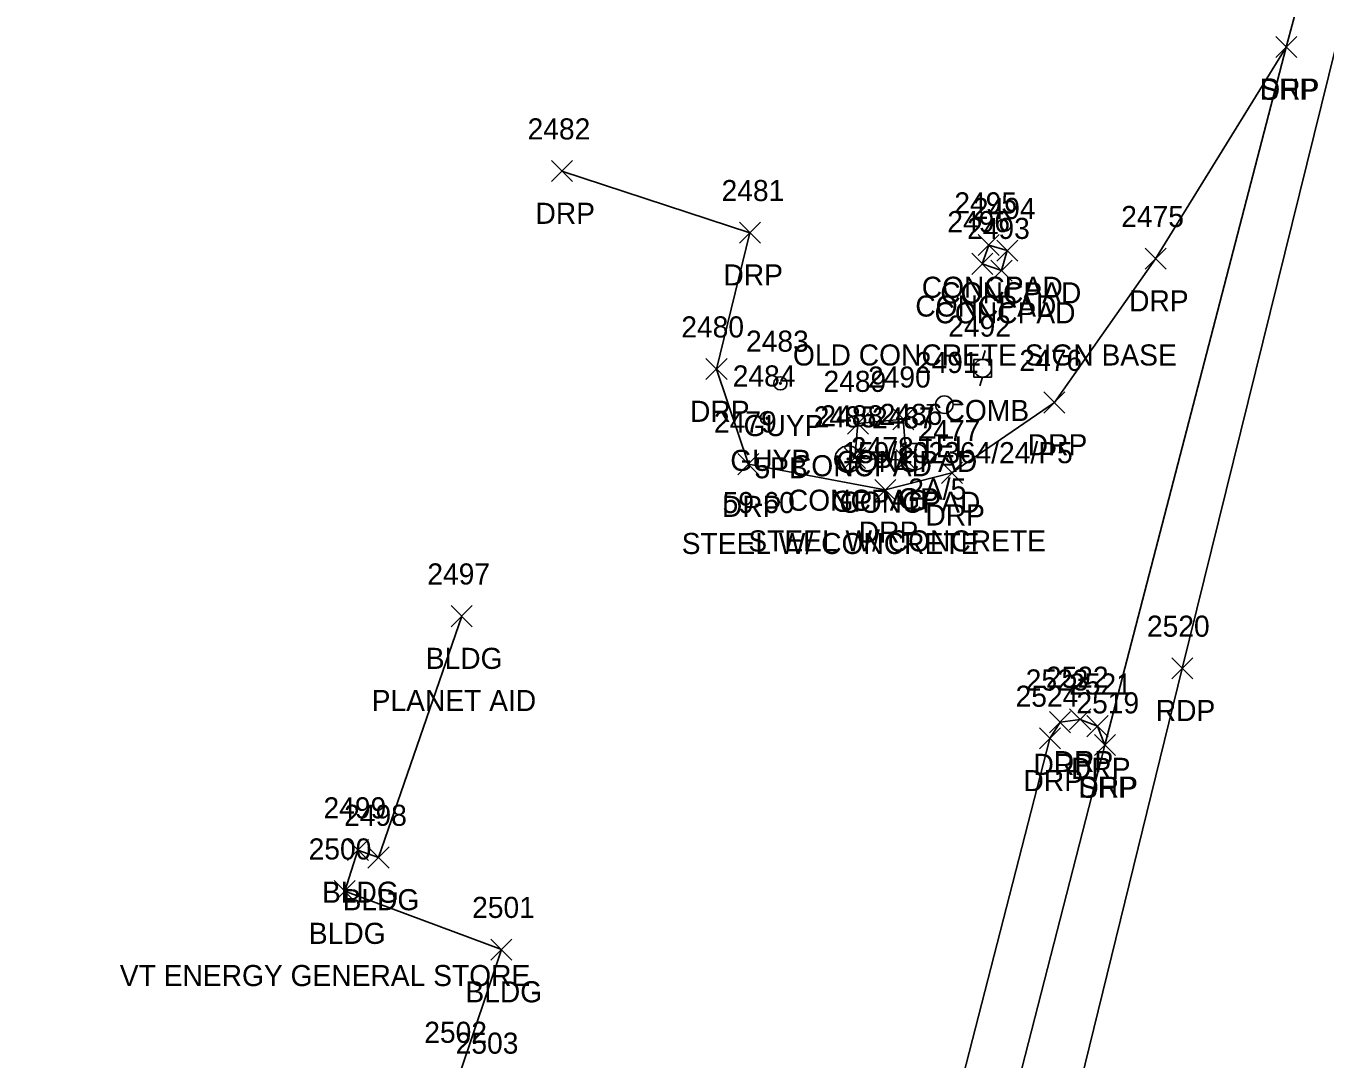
# Model space of a CAD drawing. Extents: x 1443071 to 1445292, y 614024 to 622563.
# Drawn here: x 1444043.4 to 1444166.6, y 620486.4 to 620584.3 of the extents above; entities that cross this region are included whole.
import ezdxf

# ---------------------------------------------------------------- set-up
doc = ezdxf.new("R2010")
doc.units = 0
for name, color, linetype in [('L_A', 7, 'Continuous'), ('L_C', 7, 'Continuous'), ('L_I', 7, 'Continuous'), ('L_TIC', 7, 'Continuous'), ('LBC', 7, 'Continuous'), ('LS', 7, 'Continuous'), ('P_A', 7, 'Continuous'), ('P_I', 7, 'Continuous'), ('P_TIC', 7, 'Continuous'), ('PET', 7, 'Continuous'), ('PSP', 7, 'Continuous'), ('R_A', 7, 'Continuous'), ('R_C', 7, 'Continuous'), ('R_I', 7, 'Continuous'), ('R_TIC', 7, 'Continuous'), ('RDP', 7, 'Continuous'), ('RGP', 7, 'Continuous'), ('U_A', 7, 'Continuous'), ('U_C', 7, 'Continuous'), ('U_I', 7, 'Continuous'), ('UP', 7, 'Continuous'), ('UPGW', 7, 'Continuous')]:
    doc.layers.add(name, color=color, linetype=linetype)

msp = doc.modelspace()

# ---------------------------------------------------------------- linework, layer by layer
at = {"layer": 'L_TIC'}
for points in [[(1444133.74, 620562.58), (1444135.74, 620564.58)], [(1444135.74, 620562.58), (1444133.74, 620564.58)], [(1444135.5, 620562.05), (1444137.5, 620564.05)], [(1444137.5, 620562.05), (1444135.5, 620564.05)], [(1444133.13, 620560.8), (1444135.13, 620562.8)], [(1444135.13, 620560.8), (1444133.13, 620562.8)], [(1444133.13, 620560.8), (1444135.13, 620562.8)], [(1444135.13, 620560.8), (1444133.13, 620562.8)], [(1444134.95, 620560.16), (1444136.95, 620562.16)], [(1444136.95, 620560.16), (1444134.95, 620562.16)], [(1444134.95, 620560.16), (1444136.95, 620562.16)], [(1444136.95, 620560.16), (1444134.95, 620562.16)], [(1444125.64, 620546.07), (1444127.64, 620548.07)], [(1444127.64, 620546.07), (1444125.64, 620548.07)], [(1444125.64, 620546.07), (1444127.64, 620548.07)], [(1444127.64, 620546.07), (1444125.64, 620548.07)], [(1444121.34, 620545.66), (1444123.34, 620547.66)], [(1444123.34, 620545.66), (1444121.34, 620547.66)], [(1444121.04, 620542.39), (1444123.04, 620544.39)], [(1444123.04, 620542.39), (1444121.04, 620544.39)], [(1444125.93, 620542.2), (1444127.93, 620544.2)], [(1444127.93, 620542.2), (1444125.93, 620544.2)], [(1444125.93, 620542.2), (1444127.93, 620544.2)], [(1444127.93, 620542.2), (1444125.93, 620544.2)], [(1444083.75, 620527.4), (1444085.75, 620529.4)], [(1444085.75, 620527.4), (1444083.75, 620529.4)], [(1444073.91, 620505.23), (1444075.91, 620507.23)], [(1444075.91, 620505.23), (1444073.91, 620507.23)], [(1444075.86, 620504.52), (1444077.86, 620506.52)], [(1444077.86, 620504.52), (1444075.86, 620506.52)], [(1444072.66, 620501.33), (1444074.66, 620503.33)], [(1444074.66, 620501.33), (1444072.66, 620503.33)], [(1444087.51, 620495.79), (1444089.51, 620497.79)], [(1444089.51, 620495.79), (1444087.51, 620497.79)]]:
    msp.add_lwpolyline(points, dxfattribs=at)
at = {"layer": 'LBC'}
msp.add_lwpolyline([(1444084.75, 620528.4), (1444076.86, 620505.52), (1444074.91, 620506.23), (1444073.66, 620502.33), (1444088.51, 620496.79), (1444084.54, 620484.95), (1444087.52, 620483.92), (1444085.41, 620477.91), (1444091.99, 620475.69), (1444085.33, 620455.76)], dxfattribs=at)
at = {"layer": 'LS'}
for points in [[(1444135.95, 620561.16), (1444136.5, 620563.05), (1444134.74, 620563.58), (1444134.13, 620561.8)], [(1444135.95, 620561.16), (1444134.13, 620561.8)], [(1444126.93, 620543.2), (1444122.04, 620543.39), (1444122.34, 620546.66), (1444126.64, 620547.07)], [(1444126.93, 620543.2), (1444126.64, 620547.07)]]:
    msp.add_lwpolyline(points, dxfattribs=at)
at = {"layer": 'P_TIC'}
for points in [[(1444161.97, 620581.35), (1444163.97, 620583.35)], [(1444163.97, 620581.35), (1444161.97, 620583.35)], [(1444152.1, 620522.45), (1444154.1, 620524.45)], [(1444154.1, 620522.45), (1444152.1, 620524.45)], [(1444144.76, 620515.18), (1444146.76, 620517.18)], [(1444146.76, 620515.18), (1444144.76, 620517.18)]]:
    msp.add_lwpolyline(points, dxfattribs=at)
at = {"layer": 'PET'}
msp.add_lwpolyline([(1444350.41, 621238.76), (1444319.14, 621126.97), (1444291.55, 621028.33), (1444258.02, 620908.98), (1444225.45, 620794.19), (1444210.22, 620737.59), (1444176.75, 620619.09), (1444153.1, 620523.45), (1444139.28, 620467.17), (1444131.97, 620435.45), (1444113.12, 620363.38), (1444103.37, 620315.76), (1444093.47, 620268.1), (1444084.86, 620222.29), (1444073.72, 620159.9), (1444065.08, 620092.83), (1444054.27, 620016.44), (1444048.57, 619960.86), (1444043.42, 619916.17), (1444073.05, 619913.75)], dxfattribs=at)
at = {"layer": 'PSP'}
msp.add_lwpolyline([(1444173.15, 620620.17), (1444162.97, 620582.35), (1444145.76, 620516.18), (1444133.67, 620469.15), (1444125.56, 620436.17), (1444114.52, 620389.82), (1444108.73, 620364.47), (1444098.18, 620317.14), (1444089.01, 620271.12), (1444079.56, 620223.77), (1444069.05, 620160.45), (1444059.79, 620093.6), (1444051.39, 620014.62), (1444046.92, 619961.11), (1444044.18, 619924.22), (1444043.48, 619922.84), (1444043.42, 619916.17)], dxfattribs=at)
at = {"layer": 'R_TIC'}
for points in [[(1444161.97, 620581.35), (1444163.97, 620583.35)], [(1444163.97, 620581.35), (1444161.97, 620583.35)], [(1444093.26, 620569.59), (1444095.26, 620571.59)], [(1444095.26, 620569.59), (1444093.26, 620571.59)], [(1444111.09, 620563.75), (1444113.09, 620565.75)], [(1444113.09, 620563.75), (1444111.09, 620565.75)], [(1444149.57, 620561.29), (1444151.57, 620563.29)], [(1444151.57, 620561.29), (1444149.57, 620563.29)], [(1444107.92, 620550.82), (1444109.92, 620552.82)], [(1444109.92, 620550.82), (1444107.92, 620552.82)], [(1444139.97, 620547.65), (1444141.97, 620549.65)], [(1444141.97, 620547.65), (1444139.97, 620549.65)], [(1444110.94, 620541.81), (1444112.94, 620543.81)], [(1444112.94, 620541.81), (1444110.94, 620543.81)], [(1444130.25, 620540.99), (1444132.25, 620542.99)], [(1444132.25, 620540.99), (1444130.25, 620542.99)], [(1444123.93, 620539.37), (1444125.93, 620541.37)], [(1444125.93, 620539.37), (1444123.93, 620541.37)], [(1444140.51, 620517.35), (1444142.51, 620519.35)], [(1444142.51, 620517.35), (1444140.51, 620519.35)], [(1444142.42, 620517.61), (1444144.42, 620519.61)], [(1444144.42, 620517.61), (1444142.42, 620519.61)], [(1444144.06, 620516.97), (1444146.06, 620518.97)], [(1444146.06, 620516.97), (1444144.06, 620518.97)], [(1444139.55, 620515.81), (1444141.55, 620517.81)], [(1444141.55, 620515.81), (1444139.55, 620517.81)], [(1444144.76, 620515.18), (1444146.76, 620517.18)], [(1444146.76, 620515.18), (1444144.76, 620517.18)]]:
    msp.add_lwpolyline(points, dxfattribs=at)
at = {"layer": 'RDP'}
for points in [[(1444162.97, 620582.35), (1444150.57, 620562.29), (1444140.97, 620548.65), (1444131.25, 620541.99), (1444124.93, 620540.37), (1444111.94, 620542.81), (1444108.92, 620551.82), (1444112.09, 620564.75), (1444094.26, 620570.59)], [(1444145.76, 620516.18), (1444145.06, 620517.97), (1444143.42, 620518.61), (1444141.51, 620518.35), (1444140.55, 620516.81), (1444128.49, 620469.93), (1444120.28, 620437.57), (1444109.05, 620390.35), (1444109.61, 620388.46), (1444110.93, 620387.66), (1444112.9, 620387.9), (1444114.52, 620389.82)]]:
    msp.add_lwpolyline(points, dxfattribs=at)
at = {"layer": 'RGP'}
for p, q in [((1444121.4, 620543.29), (1444121.4, 620543.29)), ((1444127.72, 620543.53), (1444127.72, 620543.53))]:
    msp.add_line(p, q, dxfattribs=at)
for centre, radius in [((1444121.4, 620543.29), 1.25), ((1444127.72, 620543.53), 1.25), ((1444121.4, 620543.29), 0.0833), ((1444127.72, 620543.53), 0.0833)]:
    msp.add_circle(centre, radius, dxfattribs=at)
at = {"layer": 'UP'}
for p, q in [((1444133.33, 620551.07), (1444133.33, 620552.73)), ((1444133.33, 620552.73), (1444134.99, 620552.73)), ((1444134.41, 620553.57), (1444134.16, 620552.73)), ((1444134.99, 620552.73), (1444134.99, 620551.07)), ((1444134.16, 620551.9), (1444134.16, 620551.9)), ((1444134.99, 620551.07), (1444133.33, 620551.07)), ((1444133.91, 620550.23), (1444134.16, 620551.07)), ((1444128.87, 620548.44), (1444129.69, 620548.44)), ((1444130.53, 620548.45), (1444130.53, 620548.45)), ((1444132.19, 620548.45), (1444131.36, 620548.45)), ((1444131.36, 620548.45), (1444131.36, 620548.45)), ((1444132.19, 620548.45), (1444132.19, 620548.45))]:
    msp.add_line(p, q, dxfattribs=at)
for centre in [(1444134.16, 620551.9), (1444130.53, 620548.45)]:
    msp.add_circle(centre, 0.833, dxfattribs=at)
at = {"layer": 'UPGW'}
for centre, radius in [((1444114.98, 620550.47), 0.625), ((1444114.98, 620550.47), 0.0833), ((1444113.71, 620547.17), 0.625), ((1444113.71, 620547.17), 0.0833)]:
    msp.add_circle(centre, radius, dxfattribs=at)

# ---------------------------------------------------------------- texts
at = {"layer": 'L_A'}
for s, p in [('CONCPAD', (1444128.39, 620558.58)), ('CONCPAD', (1444130.15, 620558.05)), ('CONCPAD', (1444127.78, 620556.8)), ('CONCPAD', (1444127.78, 620556.8)), ('CONCPAD', (1444129.6, 620556.16)), ('CONCPAD', (1444129.6, 620556.16)), ('CONCPAD', (1444120.28, 620542.07)), ('CONCPAD', (1444120.28, 620542.07)), ('CONCPAD', (1444115.98, 620541.66)), ('CONCPAD', (1444115.69, 620538.39)), ('CONCPAD', (1444120.57, 620538.2)), ('CONCPAD', (1444120.57, 620538.2)), ('BLDG', (1444081.34, 620523.4)), ('BLDG', (1444071.5, 620501.23)), ('BLDG', (1444073.45, 620500.52)), ('BLDG', (1444070.25, 620497.33)), ('BLDG', (1444085.1, 620491.79))]:
    msp.add_text(s, height=2, dxfattribs=at).set_placement(p)
at = {"layer": 'L_C'}
for s, p in [('OLD CONCRETE SIGN BASE', (1444116.17, 620552.16)), ('OLD CONCRETE SIGN BASE', (1444116.17, 620552.16)), ('PLANET AID', (1444076.21, 620519.4)), ('VT ENERGY GENERAL STORE', (1444052.32, 620493.33))]:
    msp.add_text(s, height=2, dxfattribs=at).set_placement(p)
at = {"layer": 'L_I'}
for s, p in [('2495', (1444131.48, 620566.58)), ('2494', (1444133.24, 620566.05)), ('2496', (1444130.81, 620564.8)), ('2496', (1444130.81, 620564.8)), ('2493', (1444132.69, 620564.16)), ('2493', (1444132.69, 620564.16)), ('2489', (1444119.07, 620549.66)), ('2490', (1444123.29, 620550.07)), ('2490', (1444123.29, 620550.07)), ('2488', (1444118.78, 620546.39)), ('2487', (1444123.67, 620546.2)), ('2487', (1444123.67, 620546.2)), ('2497', (1444081.49, 620531.4)), ('2499', (1444071.64, 620509.23)), ('2498', (1444073.6, 620508.52)), ('2500', (1444070.23, 620505.33)), ('2501', (1444085.74, 620499.79)), ('2502', (1444081.2, 620487.95)), ('2503', (1444084.18, 620486.92)), ('2503', (1444084.18, 620486.92))]:
    msp.add_text(s, height=2, dxfattribs=at).set_placement(p)
at = {"layer": 'P_A'}
for s, p in [('SHP', (1444160.5, 620577.35)), ('RDP', (1444150.59, 620518.45)), ('SHP', (1444143.3, 620511.18))]:
    msp.add_text(s, height=2, dxfattribs=at).set_placement(p)
at = {"layer": 'P_I'}
for s, p in [('2520', (1444149.75, 620526.45)), ('2519', (1444143.06, 620519.18))]:
    msp.add_text(s, height=2, dxfattribs=at).set_placement(p)
at = {"layer": 'R_A'}
for s, p in [('DRP', (1444160.46, 620577.35)), ('DRP', (1444091.75, 620565.59)), ('DRP', (1444109.58, 620559.75)), ('DRP', (1444148.06, 620557.29)), ('DRP', (1444106.41, 620546.82)), ('DRP', (1444138.45, 620543.65)), ('GP', (1444119.83, 620538.29)), ('GP', (1444126.15, 620538.53)), ('DRP', (1444109.43, 620537.81)), ('DRP', (1444128.74, 620536.99)), ('DRP', (1444122.42, 620535.37)), ('DRP', (1444138.99, 620513.35)), ('DRP', (1444140.91, 620513.61)), ('DRP', (1444142.55, 620512.97)), ('DRP', (1444138.04, 620511.81)), ('DRP', (1444143.25, 620511.18))]:
    msp.add_text(s, height=2, dxfattribs=at).set_placement(p)
at = {"layer": 'R_C'}
for p in [(1444111.94, 620534.53), (1444105.62, 620534.29)]:
    msp.add_text('STEEL W/ CONCRETE', height=2, dxfattribs=at).set_placement(p)
at = {"layer": 'R_I'}
for s, p in [('2482', (1444091, 620573.59)), ('2481', (1444109.4, 620567.75)), ('2475', (1444147.31, 620565.29)), ('2480', (1444105.58, 620554.82)), ('2476', (1444137.65, 620551.65)), ('2479', (1444108.68, 620545.81)), ('2485', (1444118.14, 620546.29)), ('2486', (1444124.4, 620546.53)), ('2477', (1444127.99, 620544.99)), ('2478', (1444121.67, 620543.37)), ('2523', (1444138.25, 620521.35)), ('2522', (1444140.16, 620521.61)), ('2524', (1444137.29, 620519.81)), ('2521', (1444142.37, 620520.97)), ('2519', (1444143.06, 620519.18))]:
    msp.add_text(s, height=2, dxfattribs=at).set_placement(p)
at = {"layer": 'U_A'}
for s, p in [('COMB', (1444130.55, 620546.9)), ('GUYP', (1444111.49, 620545.47)), ('TEL', (1444128.09, 620543.45)), ('GUYP', (1444110.23, 620542.17))]:
    msp.add_text(s, height=2, dxfattribs=at).set_placement(p)
at = {"layer": 'U_C'}
for s, p in [('159/102364/24/P5', (1444120.85, 620542.9)), ('5PB', (1444112.52, 620541.47)), ('2A/5', (1444127.11, 620539.45)), ('59-60', (1444109.5, 620538.17))]:
    msp.add_text(s, height=2, dxfattribs=at).set_placement(p)
at = {"layer": 'U_I'}
for s, p in [('2492', (1444130.9, 620554.9)), ('2483', (1444111.72, 620553.47)), ('2491', (1444127.83, 620551.45)), ('2484', (1444110.46, 620550.17))]:
    msp.add_text(s, height=2, dxfattribs=at).set_placement(p)

doc.saveas('drawing.dxf')
